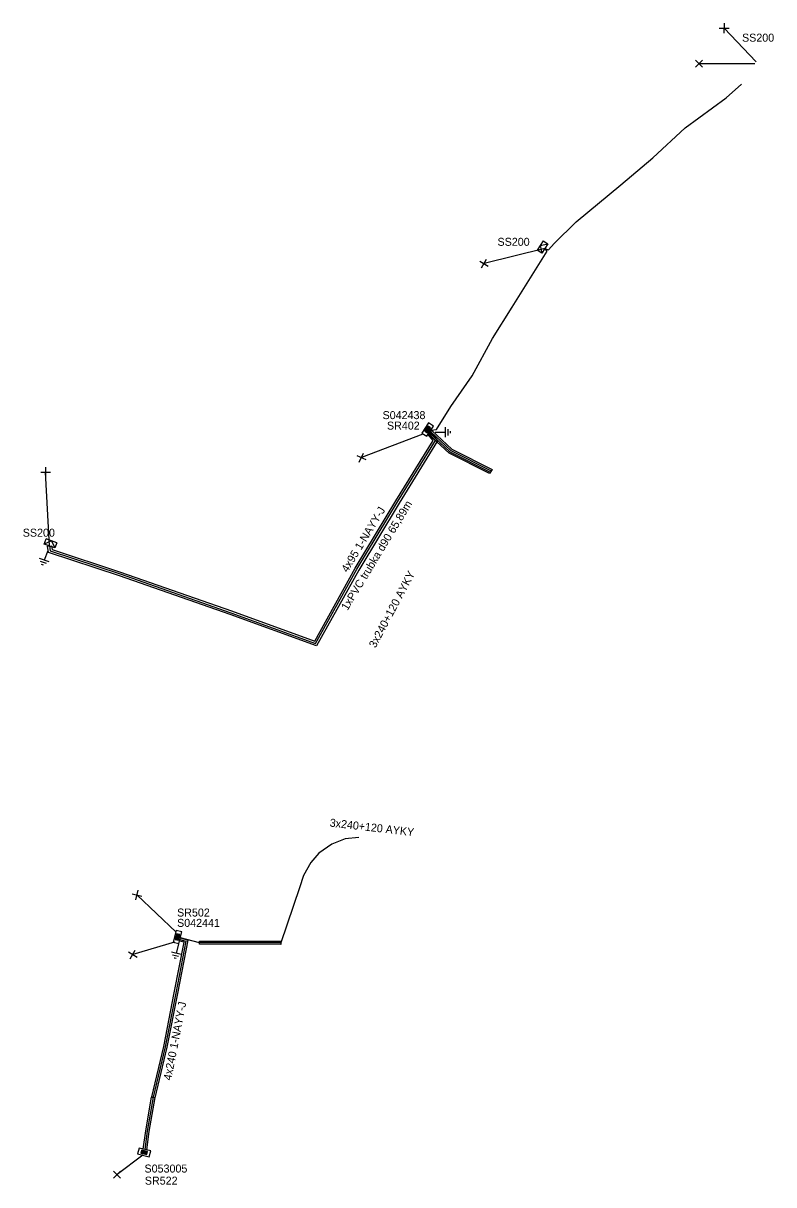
# Model space of a CAD drawing. Extents: x -737417 to -734469, y -1145580 to -1142703.
# Drawn here: x -736997.8 to -736904, y -1145111.8 to -1144966.7 of the extents above; entities that cross this region are included whole.
import ezdxf

# ---------------------------------------------------------------- set-up
doc = ezdxf.new("R2010")
doc.units = 0
for name, color, linetype in [('Vrstva 1', 7, 'Continuous'), ('Vrstva 14', 7, 'Continuous'), ('Vrstva 15', 7, 'Continuous'), ('Vrstva 20', 7, 'Continuous'), ('Vrstva 21', 7, 'Continuous'), ('Vrstva 28', 7, 'Continuous'), ('Vrstva 29', 7, 'Continuous'), ('Vrstva 30', 7, 'Continuous'), ('Vrstva 31', 7, 'Continuous'), ('Vrstva 33', 7, 'Continuous'), ('Vrstva 34', 7, 'Continuous'), ('Vrstva 5', 7, 'Continuous'), ('Vrstva 59', 7, 'Continuous'), ('Vrstva 6', 7, 'Continuous'), ('Vrstva 8', 7, 'Continuous'), ('Vrstva 9', 7, 'Continuous')]:
    doc.layers.add(name, color=color, linetype=linetype)

# ---------------------------------------------------------------- blocks, each defined once
blk = doc.blocks.new('NN800')
at = {"layer": 'Vrstva 1'}
for points in [[(-0.44, 0.44), (0.44, -0.44)], [(-0.44, -0.44), (0.44, 0.44)]]:
    blk.add_lwpolyline(points, dxfattribs=at)
blk = doc.blocks.new('NN620')
at = {"layer": 'Vrstva 8'}
for points in [[(0.75, 0), (-0.75, 0)], [(-0.75, 0), (-0.75, -0.75)], [(0.75, -0.75), (0.75, 0)], [(-0.75, -0.75), (0.75, -0.75)], [(0.37, -0.18), (-0.38, -0.18)], [(-0.38, -0.18), (-0.38, -0.56)], [(-0.38, -0.56), (0.37, -0.56)], [(0.32, -0.23), (-0.33, -0.23)], [(-0.33, -0.23), (-0.33, -0.51)], [(-0.33, -0.51), (0.32, -0.51)], [(0.27, -0.27), (-0.28, -0.27)], [(-0.28, -0.27), (-0.28, -0.46)], [(-0.28, -0.46), (0.27, -0.46)], [(0.23, -0.32), (-0.23, -0.32)], [(-0.23, -0.32), (-0.23, -0.42)], [(-0.23, -0.42), (0.23, -0.42)], [(-0.19, -0.37), (0.19, -0.37)], [(0.23, -0.42), (0.23, -0.32)], [(0.27, -0.46), (0.27, -0.27)], [(0.32, -0.51), (0.32, -0.23)], [(0.37, -0.56), (0.37, -0.18)]]:
    blk.add_lwpolyline(points, dxfattribs=at)
blk = doc.blocks.new('NN630')
at = {"layer": 'Vrstva 9'}
for points in [[(0, -0.7), (-0.7, 0)], [(-0.7, -0.7), (-0.7, 0), (0.7, 0), (0.7, -0.7)], [(-0.7, -0.7), (0.7, -0.7)], [(0, -0.7), (0.7, 0)]]:
    blk.add_lwpolyline(points, dxfattribs=at)
blk = doc.blocks.new('NN810')
at = {"layer": 'Vrstva 14'}
for points in [[(0, -0.64), (0, -1.89)], [(0.63, -1.89), (-0.62, -1.89)], [(0.39, -2.2), (-0.4, -2.2)], [(0, -2.52), (-0.12, -2.52)], [(0.14, -2.52), (0, -2.52)]]:
    blk.add_lwpolyline(points, dxfattribs=at)

msp = doc.modelspace()

# ---------------------------------------------------------------- linework, layer by layer
at = {"layer": 'Vrstva 20'}
for points in [[(-736994.25, -1145031.92), (-736994.18, -1145032.38), (-736985.61, -1145035.21), (-736971.76, -1145040.06), (-736961.36, -1145043.83), (-736956.31, -1145034.73), (-736951.22, -1145026.33), (-736946.57, -1145018.78), (-736947.22, -1145017.99), (-736946.89, -1145017.74), (-736946.03, -1145018.81), (-736950.8, -1145026.59), (-736955.87, -1145034.98), (-736961.14, -1145044.45), (-736971.92, -1145040.53), (-736985.77, -1145035.69), (-736994.62, -1145032.76), (-736994.75, -1145032)], [(-736939.54, -1145022.89), (-736944.58, -1145020.37), (-736947.15, -1145017.98), (-736946.75, -1145017.54), (-736944.24, -1145019.87), (-736939.21, -1145022.39)], [(-736978.15, -1145080.92), (-736977.22, -1145081.18), (-736978.52, -1145087.85), (-736979.83, -1145094.58), (-736981.35, -1145100.88), (-736981.73, -1145100.78), (-736980.23, -1145094.5), (-736978.92, -1145087.77), (-736977.68, -1145081.46), (-736978.26, -1145081.31)], [(-736965.6, -1145081.34), (-736965.6, -1145081.74), (-736975.78, -1145081.72), (-736975.78, -1145081.32)], [(-736981.74, -1145100.8), (-736981.34, -1145100.86), (-736982.08, -1145105.09), (-736982.38, -1145107.38), (-736982.78, -1145107.32), (-736982.48, -1145105.03)]]:
    msp.add_lwpolyline(points, close=True, dxfattribs=at)
at = {"layer": 'Vrstva 5'}
for points in [[(-736946.8, -1145017.5), (-736946.17, -1145017.39), (-736944.35, -1145014.55), (-736941.71, -1145010.69), (-736939.16, -1145006.04), (-736936.68, -1145002.12), (-736932.31, -1144995.13), (-736932.62, -1144994.8), (-736932.17, -1144994.96), (-736931.45, -1144994.19), (-736928.7, -1144991.45), (-736923.11, -1144986.86), (-736919.13, -1144983.48), (-736915.1, -1144979.73), (-736909.98, -1144975.98), (-736908.05, -1144974.28)], [(-736994.5, -1145031.96), (-736994.4, -1145032.57), (-736985.69, -1145035.45), (-736971.84, -1145040.3), (-736961.25, -1145044.14), (-736956.09, -1145034.85), (-736951.01, -1145026.46), (-736946.27, -1145018.78), (-736947.1, -1145017.94)], [(-736947.02, -1145017.83), (-736944.47, -1145020.2), (-736939.43, -1145022.72)], [(-736946.9, -1145017.67), (-736944.35, -1145020.04), (-736939.32, -1145022.56)], [(-736955.84, -1145068.39), (-736957.58, -1145068.56), (-736959.24, -1145069.21), (-736960.86, -1145070.35), (-736961.86, -1145071.48), (-736962.75, -1145073.12), (-736963.25, -1145074.68), (-736965.6, -1145081.54), (-736975.78, -1145081.52), (-736978.15, -1145080.9)], [(-736978.21, -1145081.11), (-736977.45, -1145081.32), (-736978.72, -1145087.81), (-736980.03, -1145094.54), (-736981.54, -1145100.83), (-736982.28, -1145105.06), (-736982.58, -1145107.35)]]:
    msp.add_lwpolyline(points, dxfattribs=at)
at = {"layer": 'Vrstva 59'}
for points in [[(-736906.21, -1144971.46), (-736910.23, -1144967.28)], [(-736906.4, -1144971.74), (-736913.37, -1144971.72)], [(-736932.62, -1144994.8), (-736940.21, -1144996.68)], [(-736947.88, -1145017.99), (-736955.54, -1145020.92)], [(-736994.5, -1145031.96), (-736994.98, -1145022.73)], [(-736978.69, -1145080.21), (-736983.58, -1145075.55)], [(-736978.87, -1145081.44), (-736984.1, -1145082.99)], [(-736982.84, -1145108.05), (-736986.05, -1145110.49)]]:
    msp.add_lwpolyline(points, dxfattribs=at)

# ---------------------------------------------------------------- block references
at = {"layer": 'Vrstva 15'}
for p, rotation in [((-736946.95, -1145017.76), 90.55362782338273), ((-736994.5, -1145031.96), -20.159191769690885), ((-736978.21, -1145081.02), -14.120947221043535)]:
    msp.add_blockref('NN810', p, dxfattribs=dict(at, rotation=rotation))
at = {"layer": 'Vrstva 28'}
for p, rotation in [((-736946.94, -1145017.63), -123.03445544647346), ((-736978.15, -1145080.9), -104.12094723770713), ((-736982.58, -1145107.35), -13.805049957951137)]:
    msp.add_blockref('NN620', p, dxfattribs=dict(at, rotation=rotation))
at = {"layer": 'Vrstva 31'}
for p, rotation in [((-736932.62, -1144994.8), -123.99649440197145), ((-736994.5, -1145031.96), 159.84080835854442)]:
    msp.add_blockref('NN630', p, dxfattribs=dict(at, rotation=rotation))
at = {"layer": 'Vrstva 34'}
for p, rotation in [((-736910.23, -1144967.28), -46.11316101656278), ((-736913.37, -1144971.72), -0.15421383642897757), ((-736940.21, -1144996.68), 13.91193615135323), ((-736955.54, -1145020.92), 20.93211661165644), ((-736994.98, -1145022.73), -45), ((-736983.58, -1145075.55), 30.96375551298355), ((-736984.1, -1145082.99), 14.553605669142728)]:
    msp.add_blockref('NN800', p, dxfattribs=dict(at, rotation=rotation))
msp.add_blockref('NN800', (-736986.05, -1145110.49), dxfattribs=at)

# ---------------------------------------------------------------- texts
at = {"layer": 'Vrstva 21'}
msp.add_text('1xPVC trubka d90 65,89m', height=1, rotation=58.806, dxfattribs=at).set_placement((-736957.27, -1145040.09))
at = {"layer": 'Vrstva 29'}
for s, p in [('S042438', (-736952.89, -1145016.11)), ('S042441', (-736978.56, -1145079.54)), ('S053005', (-736982.63, -1145110.23))]:
    msp.add_text(s, height=1, dxfattribs=at).set_placement(p)
at = {"layer": 'Vrstva 30'}
for s, p in [('SR402', (-736952.34, -1145017.42)), ('SR502', (-736978.56, -1145078.25)), ('SR522', (-736982.59, -1145111.74))]:
    msp.add_text(s, height=1, dxfattribs=at).set_placement(p)
at = {"layer": 'Vrstva 33'}
for p in [(-736907.98, -1144968.96), (-736938.53, -1144994.46), (-736997.84, -1145030.8)]:
    msp.add_text('SS200', height=1, dxfattribs=at).set_placement(p)
at = {"layer": 'Vrstva 6'}
for s, rotation, p in [('4x95 1-NAYY-J', 58.806, (-736957.27, -1145035.34)), ('3x240+120 AYKY', 61.963, (-736953.78, -1145044.78)), ('3x240+120 AYKY', 353.403, (-736959.53, -1145067)), ('4x240 1-NAYY-J', 78.985, (-736979.3, -1145098.77))]:
    msp.add_text(s, height=1, rotation=rotation, dxfattribs=at).set_placement(p)

doc.saveas('drawing.dxf')
